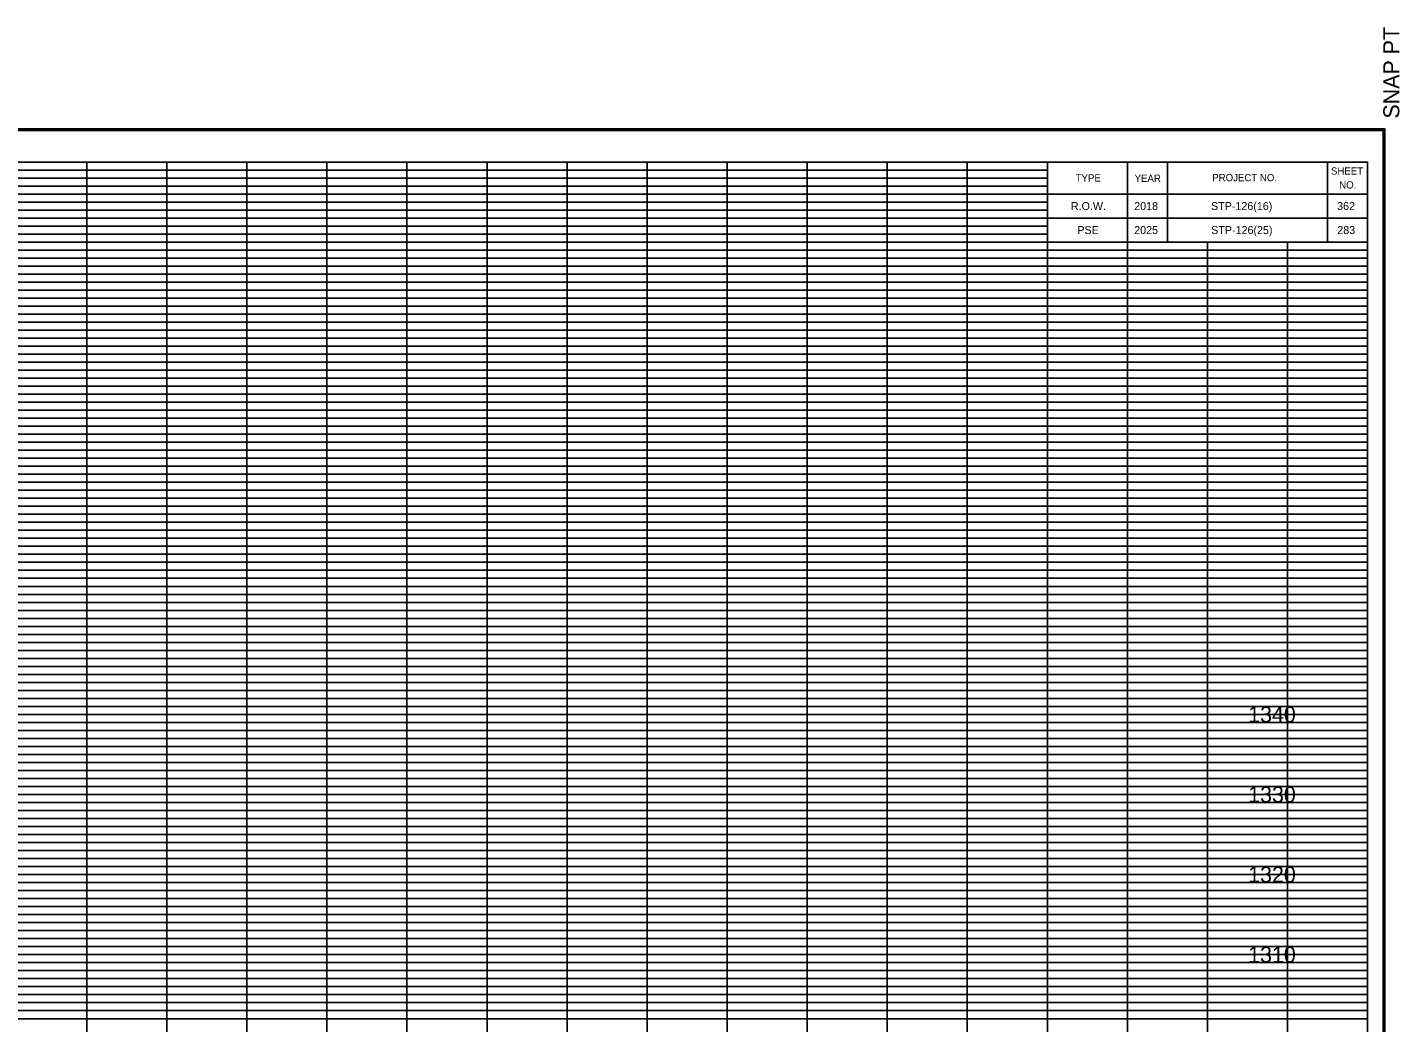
# Model space of a CAD drawing. Extents: x 980 to 1324, y 978 to 2847.
# Drawn here: x 1152.6 to 1324, y 2452.5 to 2576.8 of the extents above; entities that cross this region are included whole.
import ezdxf

# ---------------------------------------------------------------- set-up
doc = ezdxf.new("R2010")
doc.units = 0
for name, color, linetype in [('DESIGN - SCRATCH - User 1', 7, 'Continuous'), ('DESIGN - SHEET - Corner Text', 7, 'Continuous'), ('DESIGN - SHEET - Light Grid', 7, 'Continuous'), ('DESIGN - SHEET - Linework', 7, 'Continuous'), ('DESIGN - SHEET - Plot Shape', 7, 'Continuous'), ('DESIGN - TYPICAL - Text', 7, 'Continuous')]:
    doc.layers.add(name, color=color, linetype=linetype)

# ---------------------------------------------------------------- blocks, each defined once
blk = doc.blocks.new('XSTSHT')
at = {"layer": 'DESIGN - SCRATCH - User 1'}
for p, q in [((28.5, 20.45), (28.5, 20.45)), ((29.24, 20.45), (29.24, 20.45)), ((30.49, 20.45), (30.49, 20.45)), ((31.74, 20.45), (31.74, 20.45)), ((28.5, 20.15), (28.5, 20.15)), ((29.24, 20.15), (29.24, 20.15)), ((30.49, 20.15), (30.49, 20.15)), ((31.74, 20.15), (31.74, 20.15))]:
    blk.add_line(p, q, dxfattribs=at)
at = {"layer": 'DESIGN - SHEET - Light Grid'}
for p, q in [((8, 20.9), (16, 20.9)), ((8, 20.8), (16, 20.8)), ((16, 20.9), (24, 20.9)), ((16, 20.8), (24, 20.8)), ((24, 20.9), (28, 20.9)), ((24, 20.8), (28, 20.8)), ((8, 20.7), (16, 20.7)), ((8, 20.6), (16, 20.6)), ((16, 20.7), (24, 20.7)), ((16, 20.6), (24, 20.6)), ((24, 20.7), (28, 20.7)), ((24, 20.6), (28, 20.6)), ((8, 20.5), (16, 20.5)), ((8, 20.4), (16, 20.4)), ((16, 20.5), (24, 20.5)), ((16, 20.4), (24, 20.4)), ((24, 20.5), (28, 20.5)), ((24, 20.4), (28, 20.4)), ((8, 20.3), (16, 20.3)), ((16, 20.3), (24, 20.3)), ((24, 20.3), (28, 20.3)), ((8, 20.2), (16, 20.2)), ((8, 20.1), (16, 20.1)), ((16, 20.2), (24, 20.2)), ((16, 20.1), (24, 20.1)), ((24, 20.2), (28, 20.2)), ((24, 20.1), (28, 20.1)), ((8, 19.9), (16, 19.9)), ((16, 19.9), (24, 19.9)), ((24, 19.9), (32, 19.9)), ((8, 19.8), (16, 19.8)), ((16, 19.8), (24, 19.8)), ((24, 19.8), (32, 19.8)), ((8, 19.7), (16, 19.7)), ((8, 19.6), (16, 19.6)), ((16, 19.7), (24, 19.7)), ((16, 19.6), (24, 19.6)), ((24, 19.7), (32, 19.7)), ((24, 19.6), (32, 19.6)), ((8, 19.5), (16, 19.5)), ((8, 19.4), (16, 19.4)), ((16, 19.5), (24, 19.5)), ((16, 19.4), (24, 19.4)), ((24, 19.5), (32, 19.5)), ((24, 19.4), (32, 19.4)), ((8, 19.3), (16, 19.3)), ((8, 19.2), (16, 19.2)), ((16, 19.3), (24, 19.3)), ((16, 19.2), (24, 19.2)), ((24, 19.3), (32, 19.3)), ((24, 19.2), (32, 19.2)), ((8, 19.1), (16, 19.1)), ((16, 19.1), (24, 19.1)), ((24, 19.1), (32, 19.1)), ((8, 18.9), (16, 18.9)), ((16, 18.9), (24, 18.9)), ((24, 18.9), (32, 18.9)), ((8, 18.8), (16, 18.8)), ((8, 18.7), (16, 18.7)), ((16, 18.8), (24, 18.8)), ((16, 18.7), (24, 18.7)), ((24, 18.8), (32, 18.8)), ((24, 18.7), (32, 18.7)), ((8, 18.6), (16, 18.6)), ((16, 18.6), (24, 18.6)), ((24, 18.6), (32, 18.6)), ((8, 18.5), (16, 18.5)), ((8, 18.4), (16, 18.4)), ((16, 18.5), (24, 18.5)), ((16, 18.4), (24, 18.4)), ((24, 18.5), (32, 18.5)), ((24, 18.4), (32, 18.4)), ((8, 18.3), (16, 18.3)), ((8, 18.2), (16, 18.2)), ((16, 18.3), (24, 18.3)), ((16, 18.2), (24, 18.2)), ((24, 18.3), (32, 18.3)), ((24, 18.2), (32, 18.2)), ((8, 18.1), (16, 18.1)), ((16, 18.1), (24, 18.1)), ((24, 18.1), (32, 18.1)), ((8, 17.9), (16, 17.9)), ((16, 17.9), (24, 17.9)), ((24, 17.9), (32, 17.9)), ((8, 17.8), (16, 17.8)), ((8, 17.7), (16, 17.7)), ((16, 17.8), (24, 17.8)), ((16, 17.7), (24, 17.7)), ((24, 17.8), (32, 17.8)), ((24, 17.7), (32, 17.7)), ((8, 17.6), (16, 17.6)), ((8, 17.5), (16, 17.5)), ((16, 17.6), (24, 17.6)), ((16, 17.5), (24, 17.5)), ((24, 17.6), (32, 17.6)), ((24, 17.5), (32, 17.5)), ((8, 17.4), (16, 17.4)), ((16, 17.4), (24, 17.4)), ((24, 17.4), (32, 17.4)), ((8, 17.3), (16, 17.3)), ((8, 17.2), (16, 17.2)), ((16, 17.3), (24, 17.3)), ((16, 17.2), (24, 17.2)), ((24, 17.3), (32, 17.3)), ((24, 17.2), (32, 17.2)), ((8, 17.1), (16, 17.1)), ((16, 17.1), (24, 17.1)), ((24, 17.1), (32, 17.1)), ((8, 16.9), (16, 16.9)), ((8, 16.8), (16, 16.8)), ((16, 16.9), (24, 16.9)), ((16, 16.8), (24, 16.8)), ((24, 16.9), (32, 16.9)), ((24, 16.8), (32, 16.8)), ((8, 16.7), (16, 16.7)), ((16, 16.7), (24, 16.7)), ((24, 16.7), (32, 16.7)), ((8, 16.6), (16, 16.6)), ((8, 16.5), (16, 16.5)), ((16, 16.6), (24, 16.6)), ((16, 16.5), (24, 16.5)), ((24, 16.6), (32, 16.6)), ((24, 16.5), (32, 16.5)), ((8, 16.4), (16, 16.4)), ((8, 16.3), (16, 16.3)), ((16, 16.4), (24, 16.4)), ((16, 16.3), (24, 16.3)), ((24, 16.4), (32, 16.4)), ((24, 16.3), (32, 16.3)), ((8, 16.2), (16, 16.2)), ((16, 16.2), (24, 16.2)), ((24, 16.2), (32, 16.2)), ((8, 16.1), (16, 16.1)), ((16, 16.1), (24, 16.1)), ((24, 16.1), (32, 16.1)), ((8, 15.9), (16, 15.9)), ((8, 15.8), (16, 15.8)), ((16, 15.9), (24, 15.9)), ((16, 15.8), (24, 15.8)), ((24, 15.9), (32, 15.9)), ((24, 15.8), (32, 15.8)), ((8, 15.7), (16, 15.7)), ((8, 15.6), (16, 15.6)), ((16, 15.7), (24, 15.7)), ((16, 15.6), (24, 15.6)), ((24, 15.7), (32, 15.7)), ((24, 15.6), (32, 15.6)), ((8, 15.5), (16, 15.5)), ((16, 15.5), (24, 15.5)), ((24, 15.5), (32, 15.5)), ((8, 15.4), (16, 15.4)), ((8, 15.3), (16, 15.3)), ((16, 15.4), (24, 15.4)), ((16, 15.3), (24, 15.3)), ((24, 15.4), (32, 15.4)), ((24, 15.3), (32, 15.3)), ((8, 15.2), (16, 15.2)), ((8, 15.1), (16, 15.1)), ((16, 15.2), (24, 15.2)), ((16, 15.1), (24, 15.1)), ((24, 15.2), (32, 15.2)), ((24, 15.1), (32, 15.1)), ((8, 14.9), (16, 14.9)), ((8, 14.8), (16, 14.8)), ((16, 14.9), (24, 14.9)), ((16, 14.8), (24, 14.8)), ((24, 14.9), (32, 14.9)), ((24, 14.8), (32, 14.8)), ((8, 14.7), (16, 14.7)), ((8, 14.6), (16, 14.6)), ((16, 14.7), (24, 14.7)), ((16, 14.6), (24, 14.6)), ((24, 14.7), (32, 14.7)), ((24, 14.6), (32, 14.6)), ((8, 14.5), (16, 14.5)), ((8, 14.4), (16, 14.4)), ((16, 14.5), (24, 14.5)), ((16, 14.4), (24, 14.4)), ((24, 14.5), (32, 14.5)), ((24, 14.4), (32, 14.4)), ((8, 14.3), (16, 14.3)), ((16, 14.3), (24, 14.3)), ((24, 14.3), (32, 14.3)), ((8, 14.2), (16, 14.2)), ((8, 14.1), (16, 14.1)), ((16, 14.2), (24, 14.2)), ((16, 14.1), (24, 14.1)), ((24, 14.2), (32, 14.2)), ((24, 14.1), (32, 14.1)), ((8, 13.9), (16, 13.9)), ((16, 13.9), (24, 13.9)), ((24, 13.9), (32, 13.9)), ((8, 13.8), (16, 13.8)), ((16, 13.8), (24, 13.8)), ((24, 13.8), (32, 13.8)), ((8, 13.7), (16, 13.7)), ((8, 13.6), (16, 13.6)), ((16, 13.7), (24, 13.7)), ((16, 13.6), (24, 13.6)), ((24, 13.7), (32, 13.7)), ((24, 13.6), (32, 13.6)), ((8, 13.5), (16, 13.5)), ((8, 13.4), (16, 13.4)), ((16, 13.5), (24, 13.5)), ((16, 13.4), (24, 13.4)), ((24, 13.5), (32, 13.5)), ((24, 13.4), (32, 13.4)), ((8, 13.3), (16, 13.3)), ((8, 13.2), (16, 13.2)), ((16, 13.3), (24, 13.3)), ((16, 13.2), (24, 13.2)), ((24, 13.3), (32, 13.3)), ((24, 13.2), (32, 13.2)), ((8, 13.1), (16, 13.1)), ((16, 13.1), (24, 13.1)), ((24, 13.1), (32, 13.1)), ((8, 12.9), (16, 12.9)), ((16, 12.9), (24, 12.9)), ((24, 12.9), (32, 12.9)), ((8, 12.8), (16, 12.8)), ((8, 12.7), (16, 12.7)), ((16, 12.8), (24, 12.8)), ((16, 12.7), (24, 12.7)), ((24, 12.8), (32, 12.8)), ((24, 12.7), (32, 12.7)), ((8, 12.6), (16, 12.6)), ((16, 12.6), (24, 12.6)), ((24, 12.6), (32, 12.6)), ((8, 12.5), (16, 12.5)), ((8, 12.4), (16, 12.4)), ((16, 12.5), (24, 12.5)), ((16, 12.4), (24, 12.4)), ((24, 12.5), (32, 12.5)), ((24, 12.4), (32, 12.4)), ((8, 12.3), (16, 12.3)), ((8, 12.2), (16, 12.2)), ((16, 12.3), (24, 12.3)), ((16, 12.2), (24, 12.2)), ((24, 12.3), (32, 12.3)), ((24, 12.2), (32, 12.2)), ((8, 12.1), (16, 12.1)), ((16, 12.1), (24, 12.1)), ((24, 12.1), (32, 12.1)), ((8, 11.9), (16, 11.9)), ((16, 11.9), (24, 11.9)), ((24, 11.9), (32, 11.9)), ((8, 11.8), (16, 11.8)), ((8, 11.7), (16, 11.7)), ((16, 11.8), (24, 11.8)), ((16, 11.7), (24, 11.7)), ((24, 11.8), (32, 11.8)), ((24, 11.7), (32, 11.7)), ((8, 11.6), (16, 11.6)), ((8, 11.5), (16, 11.5)), ((16, 11.6), (24, 11.6)), ((16, 11.5), (24, 11.5)), ((24, 11.6), (32, 11.6)), ((24, 11.5), (32, 11.5)), ((8, 11.4), (16, 11.4)), ((16, 11.4), (24, 11.4)), ((24, 11.4), (32, 11.4)), ((8, 11.3), (16, 11.3)), ((8, 11.2), (16, 11.2)), ((16, 11.3), (24, 11.3)), ((16, 11.2), (24, 11.2)), ((24, 11.3), (32, 11.3)), ((24, 11.2), (32, 11.2)), ((8, 11.1), (16, 11.1)), ((16, 11.1), (24, 11.1)), ((24, 11.1), (32, 11.1)), ((8, 10.9), (16, 10.9)), ((8, 10.8), (16, 10.8)), ((16, 10.9), (24, 10.9)), ((16, 10.8), (24, 10.8)), ((24, 10.9), (32, 10.9)), ((24, 10.8), (32, 10.8)), ((8, 10.7), (16, 10.7)), ((16, 10.7), (24, 10.7)), ((24, 10.7), (32, 10.7)), ((8, 10.6), (16, 10.6)), ((8, 10.5), (16, 10.5)), ((16, 10.6), (24, 10.6)), ((16, 10.5), (24, 10.5)), ((24, 10.6), (32, 10.6)), ((24, 10.5), (32, 10.5)), ((8, 10.4), (16, 10.4)), ((8, 10.3), (16, 10.3)), ((16, 10.4), (24, 10.4)), ((16, 10.3), (24, 10.3)), ((24, 10.4), (32, 10.4)), ((24, 10.3), (32, 10.3))]:
    blk.add_line(p, q, dxfattribs=at)
at = {"layer": 'DESIGN - SHEET - Linework'}
for p, q in [((-1.823, 21.414), (32.217, 21.414)), ((32.217, 21.414), (32.217, -0.414)), ((16, 0), (16, 21)), ((17, 0), (17, 21)), ((18, 0), (18, 21)), ((19, 0), (19, 21)), ((20, 0), (20, 21)), ((21, 0), (21, 21)), ((22, 0), (22, 21)), ((23, 0), (23, 21)), ((24, 0), (24, 21)), ((25, 0), (25, 21)), ((26, 0), (26, 21)), ((27, 0), (27, 21)), ((0, 20), (28, 20)), ((28, 0), (28, 20)), ((29, 0), (29, 20)), ((30, 0), (30, 20)), ((31, 0), (31, 20)), ((0, 19), (32, 19)), ((0, 18), (32, 18)), ((0, 17), (32, 17)), ((0, 16), (32, 16)), ((0, 15), (32, 15)), ((0, 14), (32, 14)), ((0, 13), (32, 13)), ((0, 12), (32, 12)), ((0, 11), (32, 11))]:
    blk.add_line(p, q, dxfattribs=at)
for points in [[(0, 21), (0, 0), (32, 0), (32, 21), (0, 21)], [(28, 21), (28, 20), (32, 20), (32, 21), (31.5, 21), (31.5, 20), (29.5, 20), (29.5, 21), (29, 21), (29, 20), (32, 20), (28, 20), (28, 20.3), (32, 20.3), (32, 20.6), (28, 20.6)]]:
    blk.add_lwpolyline(points, dxfattribs=at)
at = {"layer": 'DESIGN - SHEET - Plot Shape'}
for points in [[(-1.803, 21.394), (32.197, 21.394), (32.197, -0.394), (-1.803, -0.394)], [(-0.85, 21), (32, 21), (32, -0.25), (-0.85, -0.25)]]:
    blk.add_lwpolyline(points, close=True, dxfattribs=at)
at = {"layer": 'DESIGN - SHEET - Corner Text'}
blk.add_text('  SNAP PT', height=0.2, rotation=90, dxfattribs=at).set_placement((32.397, 21.394))
for s, p in [('SHEET', (31.543, 20.843)), ('TYPE', (28.354, 20.756)), ('YEAR', (29.09, 20.752)), ('PROJECT NO.', (30.06, 20.76)), ('NO.', (31.646, 20.669))]:
    blk.add_text(s, height=0.09, dxfattribs=at).set_placement(p)

msp = doc.modelspace()

# ---------------------------------------------------------------- linework, layer by layer
at = {"layer": 'DESIGN - SHEET - Plot Shape'}
msp.add_lwpolyline([(991.5, 2347.5), (1320, 2347.5), (1320, 2560), (991.5, 2560)], close=True, dxfattribs=at)

# ---------------------------------------------------------------- block references
at = {"layer": 'DESIGN - SHEET - Plot Shape', "xscale": 10, "yscale": 10}
msp.add_blockref('XSTSHT', (1000, 2350), dxfattribs=at)

# ---------------------------------------------------------------- texts
at = {"layer": 'DESIGN - SHEET - Corner Text'}
for s, p in [('R.O.W.', (1282.94, 2554)), ('2018', (1290.85, 2554)), ('STP-126(16)', (1300.45, 2554)), ('362', (1316.2, 2554)), ('PSE', (1283.75, 2551)), ('2025', (1290.85, 2551)), ('STP-126(25)', (1300.47, 2551)), ('283', (1316.22, 2551))]:
    msp.add_text(s, height=1, dxfattribs=at).set_placement(p)
at = {"layer": 'DESIGN - TYPICAL - Text'}
for s, p in [('     1340     ', (1301.37, 2490)), ('     1330     ', (1301.37, 2480)), ('     1320     ', (1301.37, 2470)), ('     1310     ', (1301.37, 2460))]:
    msp.add_text(s, height=2, dxfattribs=at).set_placement(p)

doc.saveas('drawing.dxf')
